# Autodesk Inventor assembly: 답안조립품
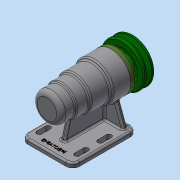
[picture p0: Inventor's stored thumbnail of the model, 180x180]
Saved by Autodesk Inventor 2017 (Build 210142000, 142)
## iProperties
Part Number: 답안조립품
Material: 일반
Document SubType Name: Assembly
Designer: MRC
Author: MRC
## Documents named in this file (12)
- C:\Users\MRC\Desktop\711009V1007\답안조립품.iam
- C:\Users\MRC\Desktop\711009V1007\본체.ipt
- C:\Users\MRC\Desktop\711009V1007\V벨트풀리.ipt
- C:\Users\MRC\Desktop\711009V1007\멈춤나사 M3.ipt
- C:\Users\MRC\Desktop\711009V1007\베어링 6004.ipt
- C:\Users\MRC\Desktop\711009V1007\베어링 51202.ipt
- C:\Users\MRC\Desktop\711009V1007\볼트 M4.ipt
- C:\Users\MRC\Desktop\711009V1007\어댑터슬리브.ipt
- C:\Users\MRC\Desktop\711009V1007\오일 실 20x35x7.ipt
- C:\Users\MRC\Desktop\711009V1007\축.ipt
- C:\Users\MRC\Desktop\711009V1007\커버.ipt
- C:\Users\MRC\Desktop\711009V1007\키 5x5.ipt
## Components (1 placed, 1 different names)
1. V벨트풀리:1
